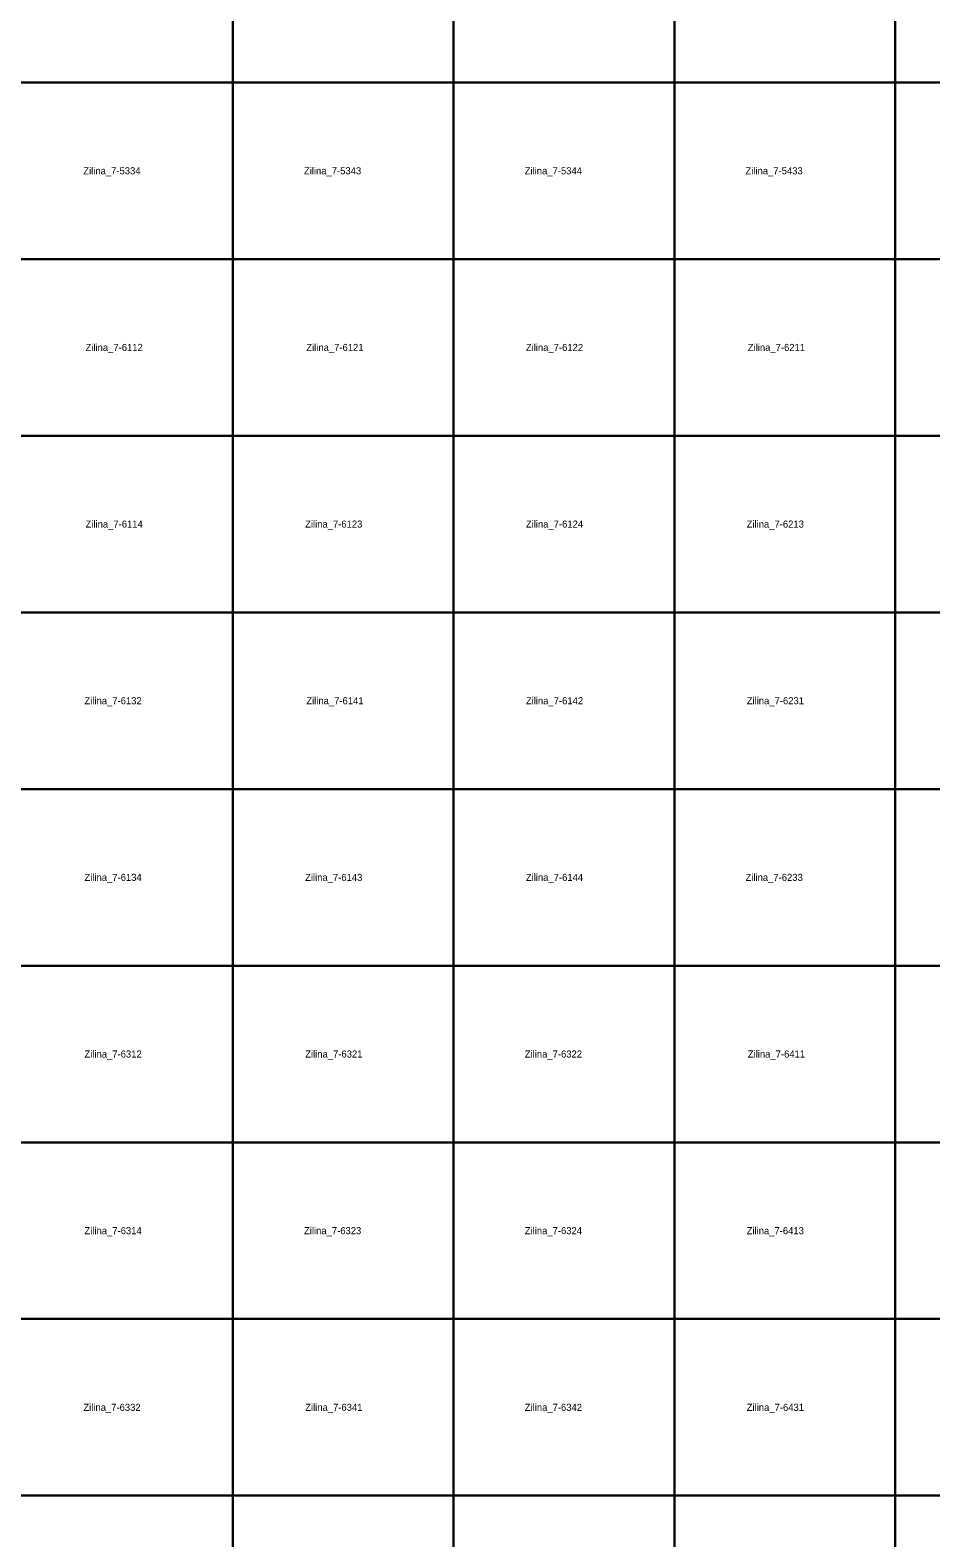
# Model space of a CAD drawing. Extents: x -445938 to -437812, y -1177250 to -1169500.
# Drawn here: x -444662 to -443387, y -1173810 to -1171676 of the extents above; entities that cross this region are included whole.
import ezdxf

# ---------------------------------------------------------------- set-up
doc = ezdxf.new("R2010")
doc.units = 0
doc.layers.add('Vrstva 4', color=7, linetype='Continuous')
doc.layers.add('Vrstva 6', color=7, linetype='Continuous')

msp = doc.modelspace()

# ---------------------------------------------------------------- linework, layer by layer
at = {"layer": 'Vrstva 4'}
for points in [[(-444375, -1171500), (-444375, -1171750), (-444687.5, -1171750), (-444687.5, -1171500)], [(-444062.5, -1171500), (-444062.5, -1171750), (-444375, -1171750), (-444375, -1171500)], [(-443750, -1171500), (-443750, -1171750), (-444062.5, -1171750), (-444062.5, -1171500)], [(-443437.5, -1171500), (-443437.5, -1171750), (-443750, -1171750), (-443750, -1171500)], [(-443125, -1171500), (-443125, -1171750), (-443437.5, -1171750), (-443437.5, -1171500)], [(-444375, -1171750), (-444375, -1172000), (-444687.5, -1172000), (-444687.5, -1171750)], [(-444062.5, -1171750), (-444062.5, -1172000), (-444375, -1172000), (-444375, -1171750)], [(-443750, -1171750), (-443750, -1172000), (-444062.5, -1172000), (-444062.5, -1171750)], [(-443437.5, -1171750), (-443437.5, -1172000), (-443750, -1172000), (-443750, -1171750)], [(-443125, -1171750), (-443125, -1172000), (-443437.5, -1172000), (-443437.5, -1171750)], [(-444375, -1172000), (-444375, -1172250), (-444687.5, -1172250), (-444687.5, -1172000)], [(-444062.5, -1172000), (-444062.5, -1172250), (-444375, -1172250), (-444375, -1172000)], [(-443750, -1172000), (-443750, -1172250), (-444062.5, -1172250), (-444062.5, -1172000)], [(-443437.5, -1172000), (-443437.5, -1172250), (-443750, -1172250), (-443750, -1172000)], [(-443125, -1172000), (-443125, -1172250), (-443437.5, -1172250), (-443437.5, -1172000)], [(-444375, -1172250), (-444375, -1172500), (-444687.5, -1172500), (-444687.5, -1172250)], [(-444062.5, -1172250), (-444062.5, -1172500), (-444375, -1172500), (-444375, -1172250)], [(-443750, -1172250), (-443750, -1172500), (-444062.5, -1172500), (-444062.5, -1172250)], [(-443437.5, -1172250), (-443437.5, -1172500), (-443750, -1172500), (-443750, -1172250)], [(-443125, -1172250), (-443125, -1172500), (-443437.5, -1172500), (-443437.5, -1172250)], [(-444375, -1172500), (-444375, -1172750), (-444687.5, -1172750), (-444687.5, -1172500)], [(-444062.5, -1172500), (-444062.5, -1172750), (-444375, -1172750), (-444375, -1172500)], [(-443750, -1172500), (-443750, -1172750), (-444062.5, -1172750), (-444062.5, -1172500)], [(-443437.5, -1172500), (-443437.5, -1172750), (-443750, -1172750), (-443750, -1172500)], [(-443125, -1172500), (-443125, -1172750), (-443437.5, -1172750), (-443437.5, -1172500)], [(-444375, -1172750), (-444375, -1173000), (-444687.5, -1173000), (-444687.5, -1172750)], [(-444062.5, -1172750), (-444062.5, -1173000), (-444375, -1173000), (-444375, -1172750)], [(-443750, -1172750), (-443750, -1173000), (-444062.5, -1173000), (-444062.5, -1172750)], [(-443437.5, -1172750), (-443437.5, -1173000), (-443750, -1173000), (-443750, -1172750)], [(-443125, -1172750), (-443125, -1173000), (-443437.5, -1173000), (-443437.5, -1172750)], [(-444375, -1173000), (-444375, -1173250), (-444687.5, -1173250), (-444687.5, -1173000)], [(-444062.5, -1173000), (-444062.5, -1173250), (-444375, -1173250), (-444375, -1173000)], [(-443750, -1173000), (-443750, -1173250), (-444062.5, -1173250), (-444062.5, -1173000)], [(-443437.5, -1173000), (-443437.5, -1173250), (-443750, -1173250), (-443750, -1173000)], [(-443125, -1173000), (-443125, -1173250), (-443437.5, -1173250), (-443437.5, -1173000)], [(-444375, -1173250), (-444375, -1173500), (-444687.5, -1173500), (-444687.5, -1173250)], [(-444062.5, -1173250), (-444062.5, -1173500), (-444375, -1173500), (-444375, -1173250)], [(-443750, -1173250), (-443750, -1173500), (-444062.5, -1173500), (-444062.5, -1173250)], [(-443437.5, -1173250), (-443437.5, -1173500), (-443750, -1173500), (-443750, -1173250)], [(-443125, -1173250), (-443125, -1173500), (-443437.5, -1173500), (-443437.5, -1173250)], [(-444375, -1173500), (-444375, -1173750), (-444687.5, -1173750), (-444687.5, -1173500)], [(-444062.5, -1173500), (-444062.5, -1173750), (-444375, -1173750), (-444375, -1173500)], [(-443750, -1173500), (-443750, -1173750), (-444062.5, -1173750), (-444062.5, -1173500)], [(-443437.5, -1173500), (-443437.5, -1173750), (-443750, -1173750), (-443750, -1173500)], [(-443125, -1173500), (-443125, -1173750), (-443437.5, -1173750), (-443437.5, -1173500)], [(-444375, -1173750), (-444375, -1174000), (-444687.5, -1174000), (-444687.5, -1173750)], [(-444062.5, -1173750), (-444062.5, -1174000), (-444375, -1174000), (-444375, -1173750)], [(-443750, -1173750), (-443750, -1174000), (-444062.5, -1174000), (-444062.5, -1173750)], [(-443437.5, -1173750), (-443437.5, -1174000), (-443750, -1174000), (-443750, -1173750)], [(-443125, -1173750), (-443125, -1174000), (-443437.5, -1174000), (-443437.5, -1173750)]]:
    msp.add_lwpolyline(points, close=True, dxfattribs=at)

# ---------------------------------------------------------------- texts
at = {"layer": 'Vrstva 6'}
for s, p in [('Zilina_7-5334', (-444586.756, -1171880)), ('Zilina_7-5343', (-444274.414, -1171880)), ('Zilina_7-5344', (-443961.914, -1171880)), ('Zilina_7-5433', (-443649.414, -1171880)), ('Zilina_7-6112', (-444583.568, -1172130)), ('Zilina_7-6121', (-444271.068, -1172130)), ('Zilina_7-6122', (-443960.261, -1172130)), ('Zilina_7-6211', (-443646.068, -1172130)), ('Zilina_7-6114', (-444583.568, -1172380)), ('Zilina_7-6123', (-444272.761, -1172380)), ('Zilina_7-6124', (-443960.261, -1172380)), ('Zilina_7-6213', (-443647.761, -1172380)), ('Zilina_7-6132', (-444585.104, -1172630)), ('Zilina_7-6141', (-444271.068, -1172630)), ('Zilina_7-6142', (-443960.261, -1172630)), ('Zilina_7-6231', (-443647.603, -1172630)), ('Zilina_7-6134', (-444585.104, -1172880)), ('Zilina_7-6143', (-444272.761, -1172880)), ('Zilina_7-6144', (-443960.261, -1172880)), ('Zilina_7-6233', (-443649.296, -1172880)), ('Zilina_7-6312', (-444585.104, -1173130)), ('Zilina_7-6321', (-444272.603, -1173130)), ('Zilina_7-6322', (-443961.796, -1173130)), ('Zilina_7-6411', (-443646.068, -1173130)), ('Zilina_7-6314', (-444585.104, -1173380)), ('Zilina_7-6323', (-444274.296, -1173380)), ('Zilina_7-6324', (-443961.796, -1173380)), ('Zilina_7-6413', (-443647.761, -1173380)), ('Zilina_7-6332', (-444586.638, -1173630)), ('Zilina_7-6341', (-444272.603, -1173630)), ('Zilina_7-6342', (-443961.796, -1173630)), ('Zilina_7-6431', (-443647.603, -1173630))]:
    msp.add_text(s, height=10, dxfattribs=at).set_placement(p)

doc.saveas('drawing.dxf')
